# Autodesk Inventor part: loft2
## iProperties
Shininess: 64.0
Length Units: 11269
Angle Units: 11279
Time Units: 11290
Mass Units: 11283
Length Display Precision: 3
Angle Display Precision: 2
Compacted: True
Part Number: loft2
Document SubType Name: Modeling
Created: 2002-12
Designer: deepak
Density: 0.0
Volumn: 0.0
Area: 0.0
PropertySet Name: Model Information
Control State: 0
Master: False
Checked Out: False
Author: deepak
